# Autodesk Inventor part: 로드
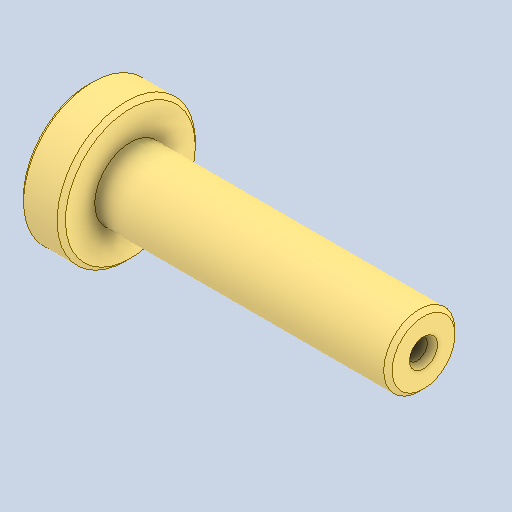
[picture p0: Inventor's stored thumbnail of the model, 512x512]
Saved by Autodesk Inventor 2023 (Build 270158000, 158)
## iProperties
Created: 2024-09
Part Number: 로드
Material: 강철, 탄소
Document SubType Name: Modeling
Designer: home
Density: 7.85 g/cm^3
Appearance: 기본값
Author: jhkim
Sending System: Autodesk Inventor 2025
Preprocessor: ST-DEVELOPER v20
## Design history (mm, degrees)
node "로드1"
node "솔리드2"
node "솔리드1"
